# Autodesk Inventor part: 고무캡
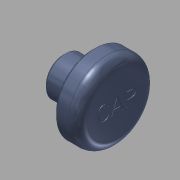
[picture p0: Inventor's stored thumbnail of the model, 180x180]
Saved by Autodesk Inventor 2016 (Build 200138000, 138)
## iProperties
Created: 2017-06
Part Number: 고무캡
Material: 고무
Document SubType Name: Modeling
Designer: mduedu
Density: 1 g/cm^3
Appearance: 고무 - 파란색 - 버전 1.1
Author: mduedu
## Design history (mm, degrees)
sketch "스케치1"
  geometry: L1 (0, 0)-(11, 0); L2 (11, 0)-(11, 8); L3 (11, 8)-(6.5, 8); L4 (0, 4)-(0, 0); L5 (0, 4)-(6, 4); L6 (6, 4)-(6, 7.5); L7 (6, 7.5)-(6.5, 7.5); L8 (6.5, 7.5)-(6.5, 8)
  constraints: 16 end point, 2 horizontal, 2 parallel, 2 perpendicular, 2 point on line, 1 vertical
  dimensions: "d0" = 16 diameter of L3 L1; "d2" = 8 diameter of L5 L1; "d6" = 5 distance between parallel lines of L2 L6; "d7" = 0.5 distance between parallel lines of L8 L6; "d8" = 15 diameter of L7 L1; "d9" = 6 distance between parallel lines of L6 L4
revolve "회전1" sketch "스케치1" stored, may be unused: angle "d10" = 90 deg
hole "구멍1" diameter "d22" = 5; stored, may be unused: countersink angle "d26" = 90 deg, drill point angle "d28" = 0 deg; dims "d23" = 6, "d24" = 4, "d25" = 2, "d27" = 6, "d30" = 10, "d31" = 10
chamfer "모따기1" distance "d13" = 0.5; stored, may be unused: second distance "d14" = 2, angle "d15" = 45 deg
fillet "모깎기3" dims "d29" = 1
fillet "모깎기1" dims "d16" = 0.1
fillet "모깎기2" dims "d17" = 2
sketch "스케치3"
  geometry: 2 further points
  constraints: 1 coincident, 1 other
feature "엠보싱1" sketch "스케치3" dims "d18" = 0.2, "d19" = 0
node "솔리드1"
